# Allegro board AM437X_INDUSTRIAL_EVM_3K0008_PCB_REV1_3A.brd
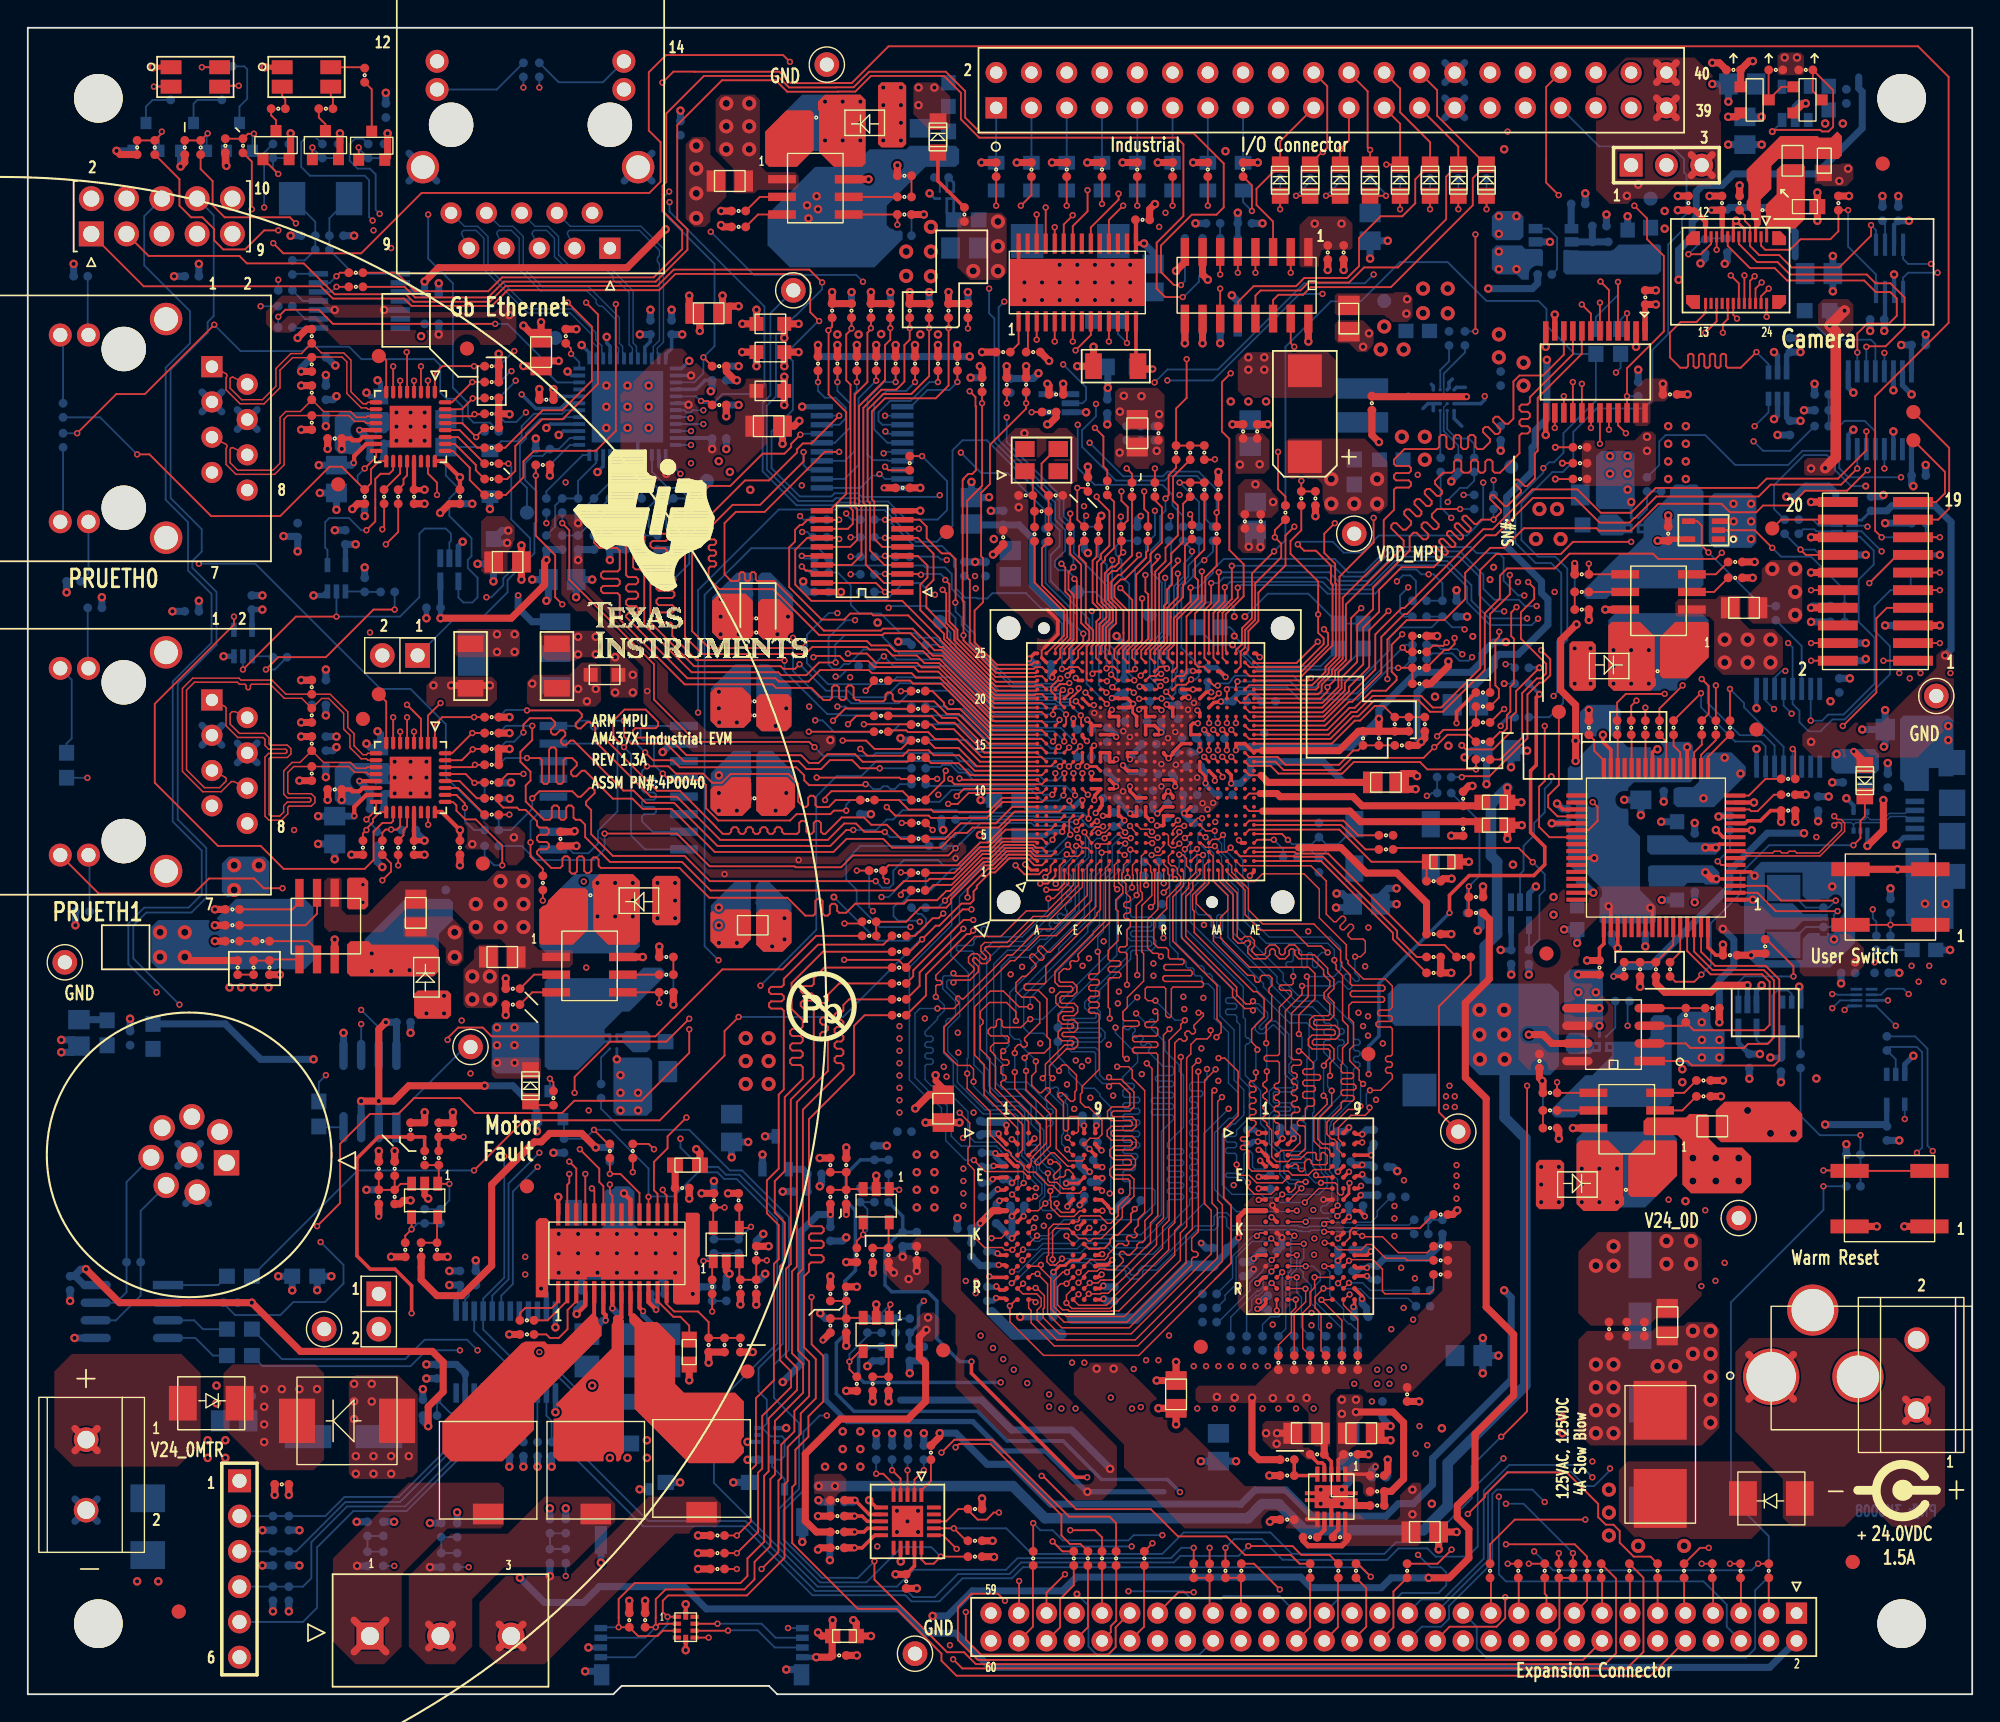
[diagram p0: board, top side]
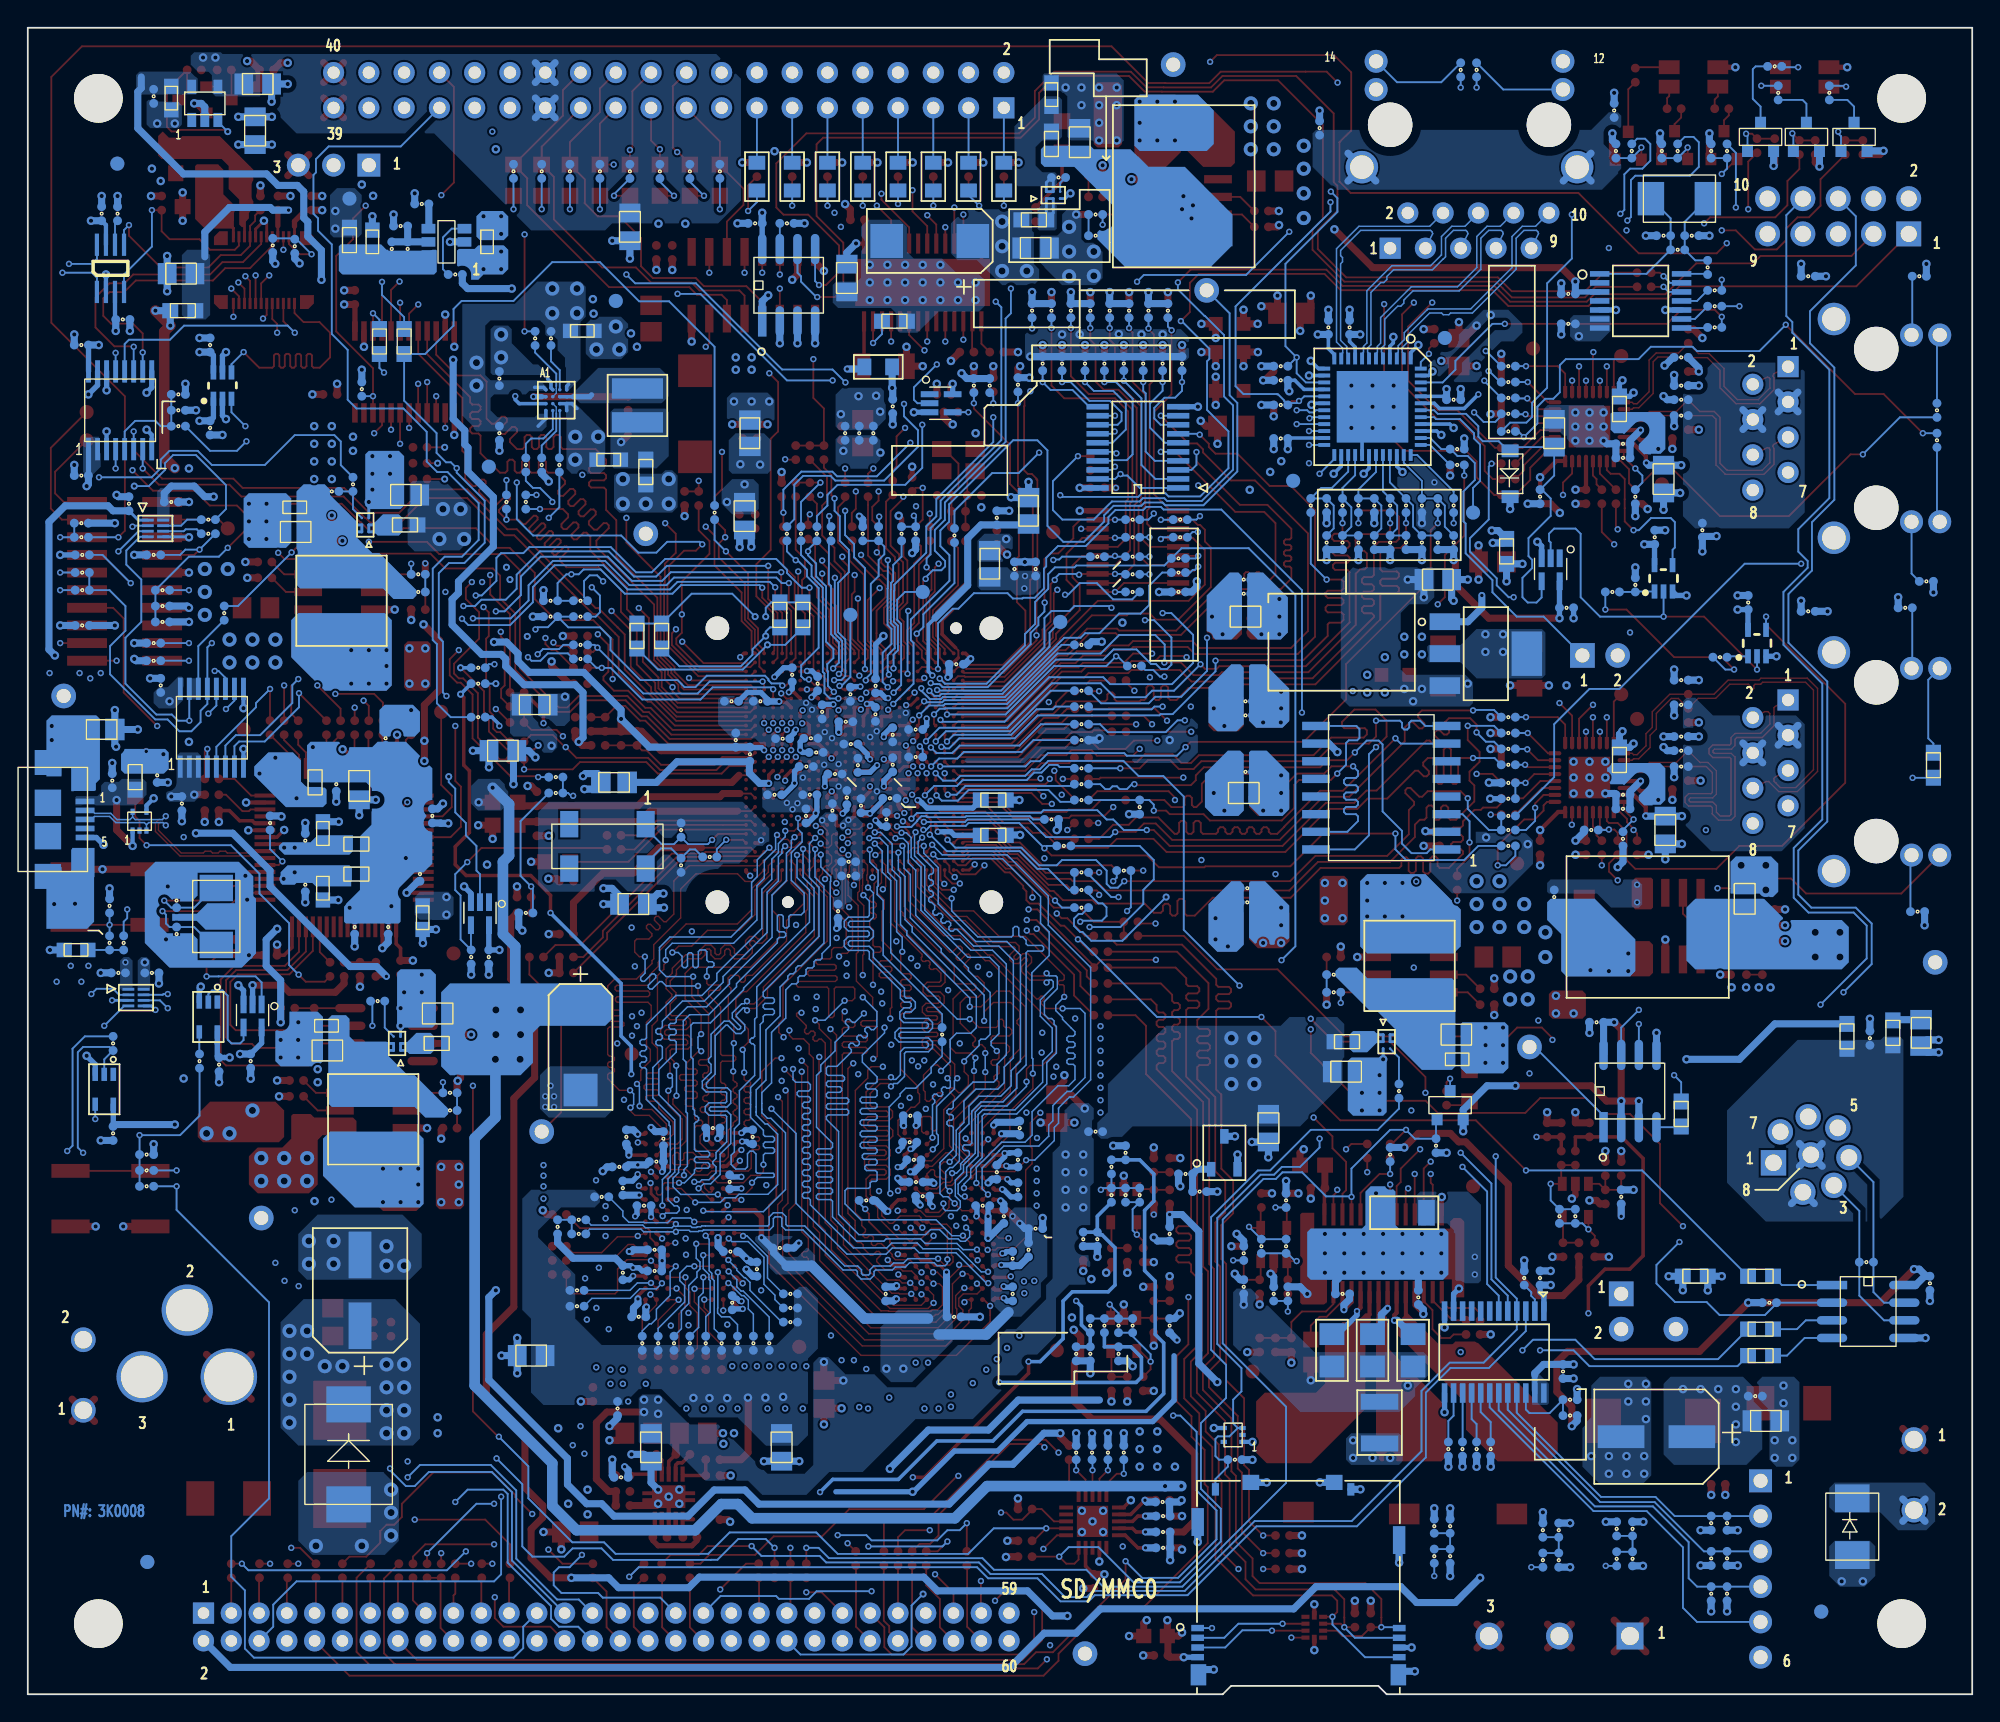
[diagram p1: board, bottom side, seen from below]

Outline 140 x 120 mm; copper layers: TOP, L2_GND, L3_SIG1, L4_SIG2, L5_PWR, BOTTOM. Coordinates in mm from the lower left corner of the outline.
Outline path: 0,120 0,0 42.16,0 42.76,0.6 53.36,0.6 53.96,0 140,0 140,120 0,120

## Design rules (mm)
net group AM437X_CAM0_DATA0: nets AM437X_CAM0_DATA0 N16702915
net group AM437X_CAM0_DATA1: nets AM437X_CAM0_DATA1 N16702921
net group AM437X_MMC0_CLK: nets AM437X_MMC0_CLK MMC_CLK
net group AM437X_MMC0_CMD: nets AM437X_MMC0_CMD MMC_CMD
net group AM437X_MMC0_DAT0: nets AM437X_MMC0_DAT0 MMC_D0
net group AM437X_MMC0_DAT1: nets AM437X_MMC0_DAT1 MMC_D1
net group AM437X_MMC0_DAT2: nets AM437X_MMC0_DAT2 MMC_D2
net group AM437X_MMC0_DAT3: nets AM437X_MMC0_DAT3 MMC_D3
net group AM437X_PRUETH0_MRCLK: nets AM437X_PRUETH0_MRCLK PRUETH0_RXCLK
net group AM437X_PRUETH0_RXD0: nets AM437X_PRUETH0_RXD0 PRUETH0_RXD0
net group AM437X_PRUETH0_RXD1: nets AM437X_PRUETH0_RXD1 PRUETH0_RXD1
net group AM437X_PRUETH0_RXD2: nets AM437X_PRUETH0_RXD2 PRUETH0_RXD2
net group AM437X_PRUETH0_RXD3: nets AM437X_PRUETH0_RXD3 PRUETH0_RXD3
net group AM437X_PRUETH0_RXDV: nets AM437X_PRUETH0_RXDV PRUETH0_RXDV
net group AM437X_PRUETH0_RXER: nets AM437X_PRUETH0_RXER PRUETH0_RXERR
net group AM437X_PRUETH0_TXCLK: nets AM437X_PRUETH0_TXCLK PRUETH0_TXCLK
net group AM437X_PRUETH0_TXD0: nets AM437X_PRUETH0_TXD0 PRUETH0_TXD0
net group AM437X_PRUETH0_TXD1: nets AM437X_PRUETH0_TXD1 PRUETH0_TXD1
net group AM437X_PRUETH0_TXD2: nets AM437X_PRUETH0_TXD2 PRUETH0_TXD2
net group AM437X_PRUETH0_TXD3: nets AM437X_PRUETH0_TXD3 PRUETH0_TXD3
net group AM437X_PRUETH0_TXEN: nets AM437X_PRUETH0_TXEN PRUETH0_TXEN
net group AM437X_PRUETH1_MRCLK: nets AM437X_PRUETH1_MRCLK PRUETH1_RXCLK
net group AM437X_PRUETH1_RXD0: nets AM437X_PRUETH1_RXD0 PRUETH1_RXD0
net group AM437X_PRUETH1_RXD1: nets AM437X_PRUETH1_RXD1 PRUETH1_RXD1
net group AM437X_PRUETH1_RXD2: nets AM437X_PRUETH1_RXD2 PRUETH1_RXD2
net group AM437X_PRUETH1_RXD3: nets AM437X_PRUETH1_RXD3 PRUETH1_RXD3
net group AM437X_PRUETH1_RXDV: nets AM437X_PRUETH1_RXDV PRUETH1_RXDV
net group AM437X_PRUETH1_RXER: nets AM437X_PRUETH1_RXER PRUETH1_RXERR
net group AM437X_PRUETH1_TXCLK: nets AM437X_PRUETH1_TXCLK PRUETH1_TXCLK
net group AM437X_PRUETH1_TXD0: nets AM437X_PRUETH1_TXD0 PRUETH1_TXD0
net group AM437X_PRUETH1_TXD1: nets AM437X_PRUETH1_TXD1 PRUETH1_TXD1
net group AM437X_PRUETH1_TXD2: nets AM437X_PRUETH1_TXD2 PRUETH1_TXD2
net group AM437X_PRUETH1_TXD3: nets AM437X_PRUETH1_TXD3 PRUETH1_TXD3
net group AM437X_PRUETH1_TXEN: nets AM437X_PRUETH1_TXEN PRUETH1_TXEN
net group AM437X_QSPI_CLK: nets AM437X_QSPI_CLK SPIMEM_CLK
net group AM437X_QSPI_CSN: nets AM437X_QSPI_CSN SPIMEM_CS
net group AM437X_QSPI_D0: nets AM437X_QSPI_D0 SPIMEM_D0
net group AM437X_QSPI_D1: nets AM437X_QSPI_D1 SPIMEM_D1
net group AM437X_QSPI_D2: nets AM437X_QSPI_D2 SPIMEM_D2
net group AM437X_QSPI_D3: nets AM437X_QSPI_D3 SPIMEM_D3
net group AM437X_RGMII1_RD0: nets AM437X_RGMII1_RD0 ETH1_RXD0
net group AM437X_RGMII1_RD1: nets AM437X_RGMII1_RD1 ETH1_RXD1
net group AM437X_RGMII1_RD2: nets AM437X_RGMII1_RD2 ETH1_RXD2
net group AM437X_RGMII1_RD3: nets AM437X_RGMII1_RD3 ETH1_RXD3
net group AM437X_RGMII1_RXCLK: nets AM437X_RGMII1_RXCLK ETH1_RXCLK
net group AM437X_RGMII1_RXCTL: nets AM437X_RGMII1_RXCTL ETH1_RXDV
net group AM437X_RGMII1_TD0: nets AM437X_RGMII1_TD0 ETH1_TXD0
net group AM437X_RGMII1_TD1: nets AM437X_RGMII1_TD1 ETH1_TXD1
net group AM437X_RGMII1_TD2: nets AM437X_RGMII1_TD2 ETH1_TXD2
net group AM437X_RGMII1_TD3: nets AM437X_RGMII1_TD3 ETH1_TXD3
net group AM437X_RGMII1_TXCLK: nets AM437X_RGMII1_TXCLK ETH1_TXCLK
net group AM437X_RGMII1_TXCTL: nets AM437X_RGMII1_TXCTL ETH1_TXEN
net group CAM0: nets AM437X_CAM0_HSYNC AM437X_CAM0_VSYNC
net group CAM0_SENSOR: nets SENSOR_HREF SENSOR_VSYNC
net group DDR_CKE: nets DDR_CKE DDR_CKE0
net group AIN: nets AM437X_AIN0 AM437X_AIN1 AM437X_AIN2 AM437X_AIN3 AM437X_AIN4 AM437X_AIN5 AM437X_AIN6 AM437X_AIN7
net group AM437X_PRUETH_MDCLK: nets AM437X_PRUETH_MDCLK PRUETH0_MDC PRUETH1_MDC
net group AM437X_PRUETH_MDDATA: nets AM437X_PRUETH_MDDATA PRUETH0_MDIO PRUETH1_MDIO
net group CLK: nets AM437X_OSC0_IN AM437X_OSC0_OUT ETH1GB_25MHZCLK INDUS_INPUTCLK OSC0_IN OSC0_OUT PRUETH0_25MHZCLK PRUETH1_25MHZCLK RTCK SD0_CLKIN SD_CLKIN XTIN XTOUT
net group DDR_DQM: nets DDR_DQM0 DDR_DQM1 DDR_DQM2 DDR_DQM3
net group IS: nets IS_IHB1 IS_IHB2 IS_IHB3 IS_MIHB1 IS_MIHB2 IS_MIHB3
net group LCD: nets AM437X_LCD_DATA7 AM437X_LCD_HSYNC AM437X_LCD_PCLK SYSBOOT14 SYSBOOT15
net group PWR: nets AGND CAP_VDD_RTC ETH1_LDO_O FT_VBUS FTDI_VPHY FTDI_VPLL MOT_OUT1 MOT_OUT2 MOT_OUT3 MOT_PGND1 MOT_PGND2 MOT_PGND3 N11219802 N11219922 N11220684 N15840029 N16288234 N16739248 N16744367 N16744371 N16744375 N16744379 N16782266 N16839102 N17134629 N17135096 N17814979 V2_8A V2_8D_FB V2_8D_OUT V3_3MTR V3_3MTRB V5_0DENCOD VDD_COREREG VDD_MPU_OUT VDD_MPU_SENSE VDD_MPU_SENSEP VDD_TAMPER VDDA1P8_PMLDO VDDA3P3_PMLDO VDDA_ADC VDDS_CTM VDDS_TAMPER VENDAT VMTR_PWRIN VUSB_FTDI VUSB_JTAG
nets with their own width: min track width 0.102; nets DDR_RESETN
nets with their own width: min track width 0.381; nets V3_3D

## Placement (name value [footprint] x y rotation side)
C1  0.1uF  [SM-7351-CAP-0402]  56.77 113.54 0 top
C2  10uF  [SM-7351-CAP-0805]  127.06 110.42 270 top
C3  0.022uF  [SM-7351-CAP-0402]  69.72 109.79 90 top
C4  0.022uF  [SM-7351-CAP-0402]  72.26 109.79 90 top
C5  0.022uF  [SM-7351-CAP-0402]  74.8 109.79 90 top
C6  0.022uF  [SM-7351-CAP-0402]  77.34 109.79 90 top
C7  0.022uF  [SM-7351-CAP-0402]  79.88 109.79 90 top
C8  0.022uF  [SM-7351-CAP-0402]  82.42 109.79 90 top
C9  0.022uF  [SM-7351-CAP-0402]  84.96 109.79 90 top
C10  0.022uF  [SM-7351-CAP-0402]  87.5 109.79 90 top
C11  2200pF  [SM-7351-CAP-0402]  63.12 109.35 180 top
C12  10uF  [SM-7351-CAP-0805]  50.55 108.97 180 top
C13  0.01uF  [SM-7351-CAP-0402]  119.57 107.38 90 top
C14  0.01uF  [SM-7351-CAP-0402]  121.98 107.38 90 top
C15  0.01uF  [SM-7351-CAP-0402]  124.9 106.87 0 top
C16  0.01uF  [SM-7351-CAP-0402]  80.26 106.17 0 top
C17  0.01uF  [SM-7351-CAP-0402]  51.18 105.66 180 top
C18  0.01uF  [SM-7351-CAP-0402]  93.6 103.82 270 top
C19  1uF  [SM-7351-CAP-0402]  94.74 103.82 270 top
C20  0.01uF  [SM-7351-CAP-0402]  116.46 100.58 90 top
C21  10uF  [SM-7351-CAP-0805]  49.02 99.44 180 top
C22  10uF  [SM-7351-CAP-0805]  36.96 96.65 90 top
C23  10uF  [SM-7351-CAP-1206]  78.33 95.63 0 top
C24  0.01uF  [SM-7351-CAP-0402]  74.04 93.6 0 top
C25  0.01uF  [SM-7351-CAP-0402]  118.24 93.6 0 top
C26  0.1uF  [SM-7351-CAP-0402]  37.34 93.22 180 top
C27  220uF  [SMD7343-122M]  91.95 92.2 90 top
C28  10uF  [SM-7351-CAP-0805]  53.34 91.31 0 top
C29  0.01uF  [SM-7351-CAP-0402]  87.5 90.93 90 top
C30  0.01uF  [SM-7351-CAP-0402]  88.52 90.93 90 top
C31  10uF  [SM-7351-CAP-0805]  79.88 90.8 90 top
C32  0.01uF  [SM-7351-CAP-0402]  81.41 90.8 90 top
C33  0.01uF  [SM-7351-CAP-0402]  22.1 90.42 180 top
C34  0.01uF  [SM-7351-CAP-0402]  62.99 86.87 180 top
C35  24pF  [SM-7351-CAP-0402]  71.85 86.33 180 top
C36  24pF  [SM-7351-CAP-0402]  74.01 86.33 0 top
C37  0.01uF  [SM-7351-CAP-0402]  27.81 86.23 270 top
C38  0.1uF  [SM-7351-CAP-0402]  31.12 86.23 270 top
C39  0.01uF  [SM-7351-CAP-0402]  87.63 84.45 90 top
C40  0.01uF  [SM-7351-CAP-0402]  88.77 84.45 90 top
C41  0.01uF  [SM-7351-CAP-0402]  118.11 83.57 90 top
C43  10uF  [SM-7351-CAP-0805]  34.54 81.53 0 top
C44  0.01uF  [SM-7351-CAP-0402]  122.94 81.53 0 top
C45  10uF  [SM-7351-CAP-0805]  123.57 78.23 0 top
C46  2200pF  [SM-7351-CAP-0402]  111.89 78.11 0 top
C47  0.01uF  [SM-7351-CAP-0402]  52.45 77.47 180 top
C48  0.01uF  [SM-7351-CAP-0402]  52.45 76.45 180 top
C49  47uF  [SM-7351-CAP-1206]  31.88 74.04 90 top
C50  47uF  [SM-7351-CAP-1206]  38.1 74.04 270 top
C51  0.1uF  [SM-7351-CAP-0402]  117.35 73.66 180 top
C52  0.01uF  [SM-7351-CAP-0402]  52.32 71.5 180 top
C53  0.01uF  [SM-7351-CAP-0402]  52.32 70.48 180 top
C54  0.001uF  [SM-7351-CAP-0402]  98.42 69.85 270 top
C55  0.1uF  [SM-7351-CAP-0402]  99.44 69.85 270 top
C56  0.001uF  [SM-7351-CAP-0402]  96.14 68.83 90 top
C57  0.1uF  [SM-7351-CAP-0402]  97.28 68.83 90 top
C58  0.01uF  [SM-7351-CAP-0402]  22.1 65.15 180 top
C59  0.01uF  [SM-7351-CAP-0402]  52.32 64.52 180 top
C60  0.01uF  [SM-7351-CAP-0402]  103.34 64.48 90 top
C61  0.01uF  [SM-7351-CAP-0402]  126.75 63.63 0 top
C62  0.01uF  [SM-7351-CAP-0402]  103.34 62.32 270 top
C63  0.01uF  [SM-7351-CAP-0402]  38.35 61.59 270 top
C64  0.01uF  [SM-7351-CAP-0402]  27.81 60.96 270 top
C65  0.1uF  [SM-7351-CAP-0402]  31.12 60.96 270 top
C66  0.01uF  [SM-7351-CAP-0402]  101.22 58.55 0 top
C67  0.1uF  [SM-7351-CAP-0402]  40.51 57.53 0 top
C68  47nF  [SM-7351-CAP-0402]  104.27 57.4 0 top
C69  0.01uF  [SM-7351-CAP-0402]  14.73 56.52 180 top
C70  10uF  [SM-7351-CAP-0805]  27.94 56.26 270 top
C71  1uF  [SM-7351-CAP-0402]  101.22 54.74 0 top
C72  2200pF  [SM-7351-CAP-0402]  14.73 54.23 180 top
C73  0.01uF  [SM-7351-CAP-0402]  122.56 53.22 0 top
C74  10uF  [SM-7351-CAP-0805]  34.16 53.09 180 top
C75  2200pF  [SM-7351-CAP-0402]  45.97 53.09 180 top
C76  0.01uF  [SM-7351-CAP-0402]  113.16 52.33 270 top
C77  0.01uF  [SM-7351-CAP-0402]  34.92 49.66 180 top
C78  0.1uF  [SM-7351-CAP-0402]  108.84 45.59 270 top
C79  0.01uF  [SM-7351-CAP-0402]  120.65 44.2 0 top
C80  22uF  [SM-7351-CAP-0805]  65.91 42.16 270 top
C81  10uF  [SM-7351-CAP-0805]  121.28 40.89 0 top
C82  2200pF  [SM-7351-CAP-0402]  109.6 40.77 0 top
C83  180pF  [SM-7351-CAP-0402]  27.56 40.64 90 top
C84  180pF  [SM-7351-CAP-0402]  29.59 40.64 90 top
C85  100pF25V10%  [SM-7351-CAP-0402]  58.93 38.1 90 top
C86  100pF25V10%  [SM-7351-CAP-0402]  26.42 37.85 90 top
C87  0.47uF  [SM-7351-CAP-0402]  47.12 36.45 0 top
C88  0.1uF  [SM-7351-CAP-0402]  115.06 36.32 180 top
C89  0.01uF  [SM-7351-CAP-0402]  49.4 35.56 90 top
C90  0.01uF  [SM-7351-CAP-0402]  29.46 32 270 top
C91  100pF25V10%  [SM-7351-CAP-0402]  52.45 31.75 90 top
C92  0.01uF  [SM-7351-CAP-0402]  61.98 31.62 270 top
C93  100pF25V10%  [SM-7351-CAP-0402]  58.93 28.83 90 top
C94  0.01uF  [SM-7351-CAP-0402]  35.94 26.92 0 top
C95  10uF  [SM-7351-CAP-0805]  118.04 26.8 90 top
C96  0.1uF  [SM-7351-CAP-0402]  113.85 26.29 90 top
C97  0.1uF  [SM-7351-CAP-0402]  115.12 26.29 90 top
C98  1uF  [SM-7351-CAP-0402]  116.39 26.29 90 top
C99  0.1uF  [SM-7351-CAP-0402]  35.94 25.91 0 top
C100  0.47uF  [SM-7351-CAP-0402]  50.16 25.15 270 top
C101  0.01uF  [SM-7351-CAP-0402]  61.98 22.35 270 top
C102  22uF  [SM-7351-CAP-0805]  82.68 21.59 270 top
C103  0.1uF  [SM-7351-CAP-0402]  99.31 21.59 270 top
C104  10uF  [SM-7351-CAP-0805]  92.08 18.8 180 top
C105  10uF  [SM-7351-CAP-0805]  96.01 18.8 0 top
C106  0.1uF  [SM-7351-CAP-0402]  92.84 17.27 180 top
C107  0.1uF  [SM-7351-CAP-0402]  95.25 17.27 0 top
C108  10pF  [SM-7351-CAP-0402]  90.68 15.75 180 top
C109  0.001uF  [SM-7351-CAP-0402]  97.16 15.75 0 top
C110  0.001uF  [SM-7351-CAP-0402]  18.29 15.11 0 top
C111  0.001uF  [SM-7351-CAP-0402]  97.16 13.59 180 top
C112  0.1uF  [SM-7351-CAP-0402]  90.68 12.57 180 top
C113  10uF  [SM-7351-CAP-0805]  100.58 11.68 0 top
C114  0.01uF  [SM-7351-CAP-0402]  63.25 8.13 270 top
C115  4.7uF  [SM-7351-CAP-0603]  58.8 4.19 0 top
C116  0.1uF  [SM-7351-CAP-0402]  58.42 2.79 0 top
C117  10uF  [SM-7351-CAP-0805]  123.44 115.95 180 bottom
C118  1uF  [SM-7351-CAP-0603]  66.29 115.19 90 bottom
C119  0.01uF  [SM-7351-CAP-0402]  130.94 115.06 270 bottom
C120  4.7uF  [SM-7351-CAP-0603]  129.67 114.94 270 bottom
C121  0.1uF  [SM-7351-CAP-0402]  25.78 114.05 270 bottom
C122  0.1uF  [SM-7351-CAP-0402]  46.99 112.78 270 bottom
C123  10uF  [SM-7351-CAP-0805]  123.63 112.59 90 bottom
C124  22uF  [SM-7351-CAP-0805]  64.26 111.76 90 bottom
C125  0.1uF  [SM-7351-CAP-0402]  111.63 107.31 0 bottom
C126  0.01uF  [SM-7351-CAP-0402]  134.68 106.61 90 bottom
C127  0.01uF  [SM-7351-CAP-0402]  87.63 105.92 0 bottom
C128  2.2uF  [SM-7351-CAP-0805]  96.65 105.66 270 bottom
C129  18pF  [SM-7351-CAP-0402]  22.23 105.03 180 bottom
C130  18pF  [SM-7351-CAP-0402]  20.19 105.03 0 bottom
C131  220uF  [SMD7343-122M]  75.06 104.65 0 bottom
C132  2.2uF  [SM-7351-CAP-0603]  115.19 104.58 90 bottom
C133  2.2uF  [SM-7351-CAP-0603]  106.93 104.58 90 bottom
C134  10uF  [SM-7351-CAP-0805]  67.44 104.14 180 bottom
C135  15pF  [SM-7351-CAP-0402]  113.79 104.07 90 bottom
C136  10uF  [SM-7351-CAP-0805]  128.97 102.3 0 bottom
C137  4700pF  [SM-7351-CAP-0402]  11.81 102.11 180 bottom
C138  2.2uF  [SM-7351-CAP-0805]  81.03 101.98 270 bottom
C139  0.01uF  [SM-7351-CAP-0402]  29.08 100.84 0 bottom
C140  0.01uF  [SM-7351-CAP-0402]  133.16 98.99 180 bottom
C141  0.01uF  [SM-7351-CAP-0402]  29.08 98.68 0 bottom
C142  0.1uF  [SM-7351-CAP-0402]  46.35 98.42 90 bottom
C143  0.1uF  [SM-7351-CAP-0402]  44.83 98.42 90 bottom
C144  10uF  [SM-7351-CAP-0603]  100.08 98.17 180 bottom
C145  0.01uF  [SM-7351-CAP-0402]  136.14 97.16 0 bottom
C146  0.01uF  [SM-7351-CAP-0402]  126.87 97.16 90 bottom
C147  0.1uF  [SM-7351-CAP-0402]  20.95 96.27 0 bottom
C148  0.1uF  [SM-7351-CAP-0402]  106.05 94.74 90 bottom
C149  0.1uF  [SM-7351-CAP-0402]  49.78 94.61 0 bottom
C150  0.1uF  [SM-7351-CAP-0402]  20.95 94.23 0 bottom
C151  1uF  [SM-7351-CAP-0402]  129.16 93.6 180 bottom
C152  0.01uF  [SM-7351-CAP-0402]  37.34 93.22 180 bottom
C153  0.1uF  [SM-7351-CAP-0402]  20.95 93.22 0 bottom
C154  0.001uF  [SM-7351-CAP-0402]  77.72 92.74 270 bottom
C155  0.1uF  [SM-7351-CAP-0402]  20.95 92.08 0 bottom
C156  0.01uF  [SM-7351-CAP-0402]  126.87 91.19 270 bottom
C157  0.1uF  [SM-7351-CAP-0402]  106.05 90.8 270 bottom
C158  0.01uF  [SM-7351-CAP-0402]  81.15 90.8 90 bottom
C159  0.01uF  [SM-7351-CAP-0402]  80.14 90.8 90 bottom
C160  0.01uF  [SM-7351-CAP-0402]  79.12 90.8 90 bottom
C161  10uF  [SM-7351-CAP-0805]  30.1 90.8 90 bottom
C162  0.1uF  [SM-7351-CAP-0402]  49.78 90.42 0 bottom
C163  0.1uF  [SM-7351-CAP-0402]  25.15 90.04 0 bottom
C164  0.1uF  [SM-7351-CAP-0402]  25.15 89.03 0 bottom
C165  10uF  [SM-7351-CAP-0603]  98.17 88.9 0 bottom
C166  0.01uF  [SM-7351-CAP-0402]  136.14 87.76 0 bottom
C167  10uF  [SM-7351-CAP-0805]  22.23 87.5 270 bottom
C168  10uF  [SM-7351-CAP-0805]  112.78 86.36 0 bottom
C169  0.01uF  [SM-7351-CAP-0402]  129.67 85.85 180 bottom
C170  0.01uF  [SM-7351-CAP-0402]  132.72 85.72 90 bottom
C171  1uF  [SM-7351-CAP-0603]  120.78 85.47 0 bottom
C172  10uF  [SM-7351-CAP-0805]  88.39 84.84 90 bottom
C173  0.01uF  [SM-7351-CAP-0402]  70.23 84.71 90 bottom
C174  0.1uF  [SM-7351-CAP-0402]  136.14 84.33 180 bottom
C175  22uF  [SM-7351-CAP-0805]  120.72 83.69 0 bottom
C176  100pF25V10%  [SM-7351-CAP-0402]  79.88 83.57 90 bottom
C177  100pF25V10%  [SM-7351-CAP-0402]  76.07 83.57 270 bottom
C178  0.01uF  [SM-7351-CAP-0402]  22.86 83.31 90 bottom
C179  0.01uF  [SM-7351-CAP-0402]  68.96 81.03 90 bottom
C180  0.01uF  [SM-7351-CAP-0402]  67.44 81.03 90 bottom
C181  0.01uF  [SM-7351-CAP-0402]  52.45 80.26 180 bottom
C182  10uF  [SM-7351-CAP-0805]  38.48 80.26 180 bottom
C183  0.01uF  [SM-7351-CAP-0402]  57.15 79.38 180 bottom
C184  0.01uF  [SM-7351-CAP-0402]  52.45 79.25 180 bottom
C185  0.01uF  [SM-7351-CAP-0402]  16.13 78.61 90 bottom
C186  1uF  [SM-7351-CAP-0402]  130.3 78.36 180 bottom
C187  0.01uF  [SM-7351-CAP-0402]  29.21 78.23 180 bottom
C188  4700pF  [SM-7351-CAP-0402]  11.81 77.98 180 bottom
C189  10uF  [SM-7351-CAP-0805]  52.32 77.6 180 bottom
C190  0.01uF  [SM-7351-CAP-0402]  136.08 76.96 180 bottom
C191  1uF  [SM-7351-CAP-0402]  64.14 75.56 180 bottom
C192  0.01uF  [SM-7351-CAP-0402]  73.15 74.17 180 bottom
C193  0.01uF  [SM-7351-CAP-0402]  84.96 73.41 90 bottom
C194  0.1uF  [SM-7351-CAP-0402]  20.95 73.02 0 bottom
C195  0.01uF  [SM-7351-CAP-0402]  83.13 72.77 90 bottom
C196  0.01uF  [SM-7351-CAP-0402]  130.43 72.64 90 bottom
C197  0.01uF  [SM-7351-CAP-0402]  78.96 72.61 90 bottom
C198  0.01uF  [SM-7351-CAP-0402]  80.77 72.01 270 bottom
C199  0.01uF  [SM-7351-CAP-0402]  89.33 71.5 0 bottom
C200  0.01uF  [SM-7351-CAP-0402]  87.25 71.5 0 bottom
C201  0.01uF  [SM-7351-CAP-0402]  52.32 71.5 180 bottom
C202  0.01uF  [SM-7351-CAP-0402]  82.8 70.74 270 bottom
C203  0.01uF  [SM-7351-CAP-0402]  78.97 70.56 270 bottom
C204  0.01uF  [SM-7351-CAP-0402]  52.32 70.48 180 bottom
C205  0.01uF  [SM-7351-CAP-0402]  81.1 70.03 180 bottom
C206  0.01uF  [SM-7351-CAP-0402]  76.07 69.47 0 bottom
C207  0.01uF  [SM-7351-CAP-0402]  77.72 69.09 270 bottom
C208  0.1uF  [SM-7351-CAP-0402]  20.95 68.96 0 bottom
C209  0.01uF  [SM-7351-CAP-0402]  114.23 68.83 90 bottom
C210  0.01uF  [SM-7351-CAP-0402]  83.62 68.83 180 bottom
C211  0.01uF  [SM-7351-CAP-0402]  85.65 68.81 0 bottom
C212  1uF  [SM-7351-CAP-0402]  64.14 68.71 180 bottom
C213  0.01uF  [SM-7351-CAP-0402]  80.74 68.42 0 bottom
C214  10uF  [SM-7351-CAP-0805]  105.79 67.95 0 bottom
C215  0.1uF  [SM-7351-CAP-0402]  20.95 67.95 0 bottom
C216  0.01uF  [SM-7351-CAP-0402]  83.24 67.82 180 bottom
C217  0.01uF  [SM-7351-CAP-0402]  88.01 67.69 90 bottom
C218  1uF  [SM-7351-CAP-0402]  76.07 67.49 0 bottom
C219  0.01uF  [SM-7351-CAP-0402]  77.72 66.93 90 bottom
C220  0.01uF  [SM-7351-CAP-0402]  80.23 66.9 90 bottom
C221  0.01uF  [SM-7351-CAP-0402]  83.95 66.8 180 bottom
C222  0.1uF  [SM-7351-CAP-0402]  20.95 66.8 0 bottom
C223  0.01uF  [SM-7351-CAP-0402]  52.32 66.42 180 bottom
C224  0.01uF  [SM-7351-CAP-0402]  81.88 66.26 180 bottom
C225  0.01uF  [SM-7351-CAP-0402]  130.68 66.17 270 bottom
C226  0.01uF  [SM-7351-CAP-0402]  133.92 65.79 90 bottom
C227  0.01uF  [SM-7351-CAP-0402]  117.79 65.53 270 bottom
C228  2.2uF  [SM-7351-CAP-0805]  116.14 65.41 270 bottom
C229  10uF  [SM-7351-CAP-0805]  52.45 64.9 180 bottom
C230  0.01uF  [SM-7351-CAP-0402]  86.23 64.77 0 bottom
C231  0.01uF  [SM-7351-CAP-0402]  83.69 64.77 0 bottom
C232  0.1uF  [SM-7351-CAP-0402]  25.15 64.77 0 bottom
C233  0.01uF  [SM-7351-CAP-0402]  81.03 64.57 90 bottom
C234  0.01uF  [SM-7351-CAP-0402]  77.93 64.52 180 bottom
C235  0.01uF  [SM-7351-CAP-0402]  128.91 64.14 270 bottom
C236  0.01uF  [SM-7351-CAP-0402]  80.01 63.98 90 bottom
C237  0.1uF  [SM-7351-CAP-0402]  25.15 63.75 0 bottom
C238  0.01uF  [SM-7351-CAP-0402]  82.07 63.63 90 bottom
C239  0.01uF  [SM-7351-CAP-0402]  110.87 63.25 90 bottom
C240  0.01uF  [SM-7351-CAP-0402]  83.97 63.25 90 bottom
C241  0.01uF  [SM-7351-CAP-0402]  78.18 62.99 90 bottom
C242  0.01uF  [SM-7351-CAP-0402]  66.29 62.99 180 bottom
C243  15pF  [SM-7351-CAP-0402]  92.96 62.23 90 bottom
C244  10uF  [SM-7351-CAP-0805]  22.1 62.23 270 bottom
C245  4.7uF  [SM-7351-CAP-0603]  118.75 61.98 270 bottom
C246  0.01uF  [SM-7351-CAP-0402]  120.02 61.47 270 bottom
C247  0.01uF  [SM-7351-CAP-0402]  80.9 59.94 0 bottom
C248  15pF  [SM-7351-CAP-0402]  92.96 59.69 270 bottom
C249  0.01uF  [SM-7351-CAP-0402]  111.76 59.06 270 bottom
C250  0.01uF  [SM-7351-CAP-0402]  120.02 58.3 90 bottom
C251  4.7uF  [SM-7351-CAP-0603]  118.75 58.04 90 bottom
C252  0.01uF  [SM-7351-CAP-0402]  52.2 58.04 180 bottom
C253  0.1uF  [SM-7351-CAP-0402]  30.1 57.4 270 bottom
C254  22uF  [SM-7351-CAP-0805]  16.38 57.28 90 bottom
C255  18pF  [SM-7351-CAP-0402]  129.29 57.15 90 bottom
C256  0.01uF  [SM-7351-CAP-0402]  52.2 57.02 180 bottom
C257  10uF  [SM-7351-CAP-0805]  96.39 56.9 0 bottom
C258  4.7uF  [SM-7351-CAP-0603]  111.57 55.92 270 bottom
C259  0.01uF  [SM-7351-CAP-0402]  116.46 55.25 270 bottom
C260  0.01uF  [SM-7351-CAP-0402]  114.05 55.25 90 bottom
C261  18pF  [SM-7351-CAP-0402]  129.29 54.74 270 bottom
C262  1uF  [SM-7351-CAP-0603]  136.53 53.59 0 bottom
C263  0.01uF  [SM-7351-CAP-0402]  106.81 53.09 270 bottom
C264  0.01uF  [SM-7351-CAP-0402]  133.48 51.94 0 bottom
C265  0.01uF  [SM-7351-CAP-0402]  131.06 51.94 180 bottom
C266  10uF  [SM-7351-CAP-0805]  110.49 49.02 0 bottom
C267  0.01uF  [SM-7351-CAP-0402]  27.05 48.39 0 bottom
C268  1uF  [SM-7351-CAP-0603]  118.49 48.13 0 bottom
C269  22uF  [SM-7351-CAP-0805]  37.14 47.5 180 bottom
C270  0.01uF  [SM-7351-CAP-0402]  7.37 47.24 90 bottom
C271  220uF  [SMD7343-122M]  100.2 46.61 270 bottom
C272  22uF  [SM-7351-CAP-0805]  118.43 46.35 0 bottom
C273  1uF  [SM-7351-CAP-0603]  37.08 45.72 180 bottom
C274  0.01uF  [SM-7351-CAP-0402]  123.95 45.59 90 bottom
C275  0.01uF  [SM-7351-CAP-0402]  126.23 45.34 90 bottom
C276  10uF  [SM-7351-CAP-0805]  45.09 44.83 180 bottom
C277  0.01uF  [SM-7351-CAP-0402]  76.45 41.66 0 bottom
C278  0.01uF  [SM-7351-CAP-0402]  90.68 40.77 0 bottom
C279  0.01uF  [SM-7351-CAP-0402]  68.58 40.77 270 bottom
C280  10uF  [SM-7351-CAP-0805]  50.67 40.77 270 bottom
C281  0.01uF  [SM-7351-CAP-0402]  133.86 40.39 270 bottom
C282  0.01uF  [SM-7351-CAP-0402]  96.9 40.13 90 bottom
C283  0.01uF  [SM-7351-CAP-0402]  87.81 40.13 270 bottom
C284  0.01uF  [SM-7351-CAP-0402]  94.23 40 270 bottom
C285  0.01uF  [SM-7351-CAP-0402]  76.5 39.75 0 bottom
C286  180pF  [SM-7351-CAP-0402]  60.96 38.99 90 bottom
C287  1uF  [SM-7351-CAP-0402]  131.44 38.86 180 bottom
C288  0.01uF  [SM-7351-CAP-0402]  76.2 38.48 180 bottom
C289  0.01uF  [SM-7351-CAP-0402]  68.71 38.48 270 bottom
C290  0.01uF  [SM-7351-CAP-0402]  94.74 38.35 180 bottom
C291  0.01uF  [SM-7351-CAP-0402]  97.41 37.97 0 bottom
C292  0.01uF  [SM-7351-CAP-0402]  70.23 37.59 270 bottom
C293  0.47uF  [SM-7351-CAP-0402]  56.64 37.46 0 bottom
C294  0.01uF  [SM-7351-CAP-0402]  89.47 36.89 90 bottom
C295  0.01uF  [SM-7351-CAP-0402]  76.05 36.88 180 bottom
C296  0.01uF  [SM-7351-CAP-0402]  97.16 36.45 270 bottom
C297  0.01uF  [SM-7351-CAP-0402]  68.71 36.32 90 bottom
C298  100pF25V10%  [SM-7351-CAP-0402]  60.96 35.94 90 bottom
C299  0.01uF  [SM-7351-CAP-0402]  75.56 35.86 0 bottom
C300  0.001uF  [SM-7351-CAP-0402]  25.27 35.81 90 bottom
C301  0.01uF  [SM-7351-CAP-0402]  95.63 35.18 180 bottom
C302  0.01uF  [SM-7351-CAP-0402]  71.25 35.18 0 bottom
C303  10uF  [SM-7351-CAP-1206]  40.89 34.67 180 bottom
C304  0.01uF  [SM-7351-CAP-0402]  69.72 34.42 90 bottom
C305  100pF25V10%  [SM-7351-CAP-0402]  29.72 34.42 90 bottom
C306  0.1uF  [SM-7351-CAP-0402]  101.85 33.66 270 bottom
C307  0.1uF  [SM-7351-CAP-0402]  67.44 33.53 180 bottom
C308  0.001uF  [SM-7351-CAP-0402]  57.78 33.15 270 bottom
C309  180pF  [SM-7351-CAP-0402]  64.01 32.77 270 bottom
C310  100pF25V10%  [SM-7351-CAP-0402]  51.18 32.26 270 bottom
C311  0.1uF  [SM-7351-CAP-0402]  85.85 32.13 180 bottom
C312  0.1uF  [SM-7351-CAP-0402]  94.87 32 0 bottom
C313  0.1uF  [SM-7351-CAP-0402]  67.95 32 90 bottom
C314  0.01uF  [SM-7351-CAP-0402]  89.41 31.88 180 bottom
C315  0.01uF  [SM-7351-CAP-0402]  69.09 31.37 90 bottom
C316  0.01uF  [SM-7351-CAP-0402]  87.5 30.61 90 bottom
C317  0.1uF  [SM-7351-CAP-0402]  94.87 30.48 180 bottom
C318  0.01uF  [SM-7351-CAP-0402]  97.16 30.35 270 bottom
C319  0.01uF  [SM-7351-CAP-0402]  31.12 29.97 90 bottom
C320  0.01uF  [SM-7351-CAP-0402]  3.05 29.59 270 bottom
C321  0.001uF  [SM-7351-CAP-0402]  52.45 29.34 90 bottom
C322  100uF  [CAP-ALUM-D6XL7]  116.08 29.08 90 bottom
C323  0.01uF  [SM-7351-CAP-0402]  78.23 28.83 270 bottom
C324  0.01uF  [SM-7351-CAP-0402]  69.09 28.83 270 bottom
C325  180pF  [SM-7351-CAP-0402]  49.28 28.83 90 bottom
C326  0.1uF  [SM-7351-CAP-0402]  45.34 28.83 0 bottom
C327  0.1uF  [SM-7351-CAP-0402]  39.88 28.58 90 bottom
C328  0.01uF  [SM-7351-CAP-0402]  89.28 28.19 270 bottom
C329  0.01uF  [SM-7351-CAP-0402]  96.01 27.18 180 bottom
C330  0.1uF  [SM-7351-CAP-0402]  73.31 27.17 180 bottom
C331  100pF25V10%  [SM-7351-CAP-0402]  61.47 26.54 90 bottom
C332  0.001uF  [SM-7351-CAP-0402]  57.78 26.54 90 bottom
C333  180pF  [SM-7351-CAP-0402]  63.5 24.51 270 bottom
C334  180pF  [SM-7351-CAP-0402]  61.47 24.51 270 bottom
C335  10uF  [SM-7351-CAP-0805]  103.76 24.38 0 bottom
C336  0.01uF  [SM-7351-CAP-0402]  29.46 23.24 270 bottom
C337  0.1uF  [SM-7351-CAP-0402]  15.62 21.46 180 bottom
C338  0.1uF  [SM-7351-CAP-0402]  97.54 20.57 270 bottom
C339  10uF  [SM-7351-CAP-0805]  14.86 19.69 180 bottom
C340  100uF  [CAP-ALUM-D6XL7]  22.73 18.54 0 bottom
C341  10uF  [SM-7351-CAP-0805]  95.12 17.78 270 bottom
C342  10uF  [SM-7351-CAP-0805]  85.72 17.78 270 bottom
C343  0.01uF  [SM-7351-CAP-0402]  64.52 17.4 90 bottom
C344  0.01uF  [SM-7351-CAP-0402]  63.37 17.4 90 bottom
C345  0.01uF  [SM-7351-CAP-0402]  62.23 17.4 90 bottom
C346  0.01uF  [SM-7351-CAP-0402]  61.09 17.4 90 bottom
C347  0.001uF  [SM-7351-CAP-0402]  18.8 12.32 270 bottom
C348  47nF  [SM-7351-CAP-0402]  38.73 12.1 90 bottom
C349  47nF  [SM-7351-CAP-0402]  24.46 11.91 90 bottom
C350  47nF  [SM-7351-CAP-0402]  30.91 11.82 90 bottom
C351  0.001uF  [SM-7351-CAP-0402]  18.8 9.78 270 bottom
C352  0.001uF  [SM-7351-CAP-0402]  18.8 7.24 270 bottom
D1  MBR0530T1  [SOD-123]  60.26 113.16 180 top
D2  Green LED  [SM_LED_0805]  65.53 112.14 90 top
D3  Green LED  [SM_LED_0805]  90.17 109.03 90 top
D4  Green LED  [SM_LED_0805]  92.33 109.03 90 top
D5  Green LED  [SM_LED_0805]  94.49 109.03 90 top
D6  Green LED  [SM_LED_0805]  96.65 109.03 90 top
D7  Green LED  [SM_LED_0805]  98.81 109.03 90 top
D8  Green LED  [SM_LED_0805]  100.97 109.03 90 top
D9  Green LED  [SM_LED_0805]  103 109.03 90 top
D10  Green LED  [SM_LED_0805]  105.03 109.03 90 top
D11  MBR0530T1  [SOD-123]  113.86 74.04 0 top
D12  Green LED  [SM_LED_0805]  132.27 65.79 270 top
D13  MBR0530T1  [SOD-123]  44 57.15 180 top
D14  MBR0530T1  [SOD-123]  28.7 51.63 90 top
D15  Red LED  [SM_LED_0805]  36.2 43.81 90 top
D16  MBR0530T1  [SOD-123]  111.57 36.7 0 top
D17  -  [MBRS140T]  13.21 20.95 180 top
D18  -  [SMCJ26CA]  22.99 19.69 0 top
D19  -  [MBRS140T]  125.54 14.1 0 top
D20  MMSD103T1  [SOD-123]  33.27 87.88 270 bottom
D21  -  [SMCJ26CA]  116.9 17.27 270 bottom
D22  -  [MBRS140T]  8.64 12.07 270 bottom
F1  Fuse 4A  [SMDFUSEBLK]  117.54 17.27 90 top
FB1  150OHM800mA  [SM-7351-IND-0805]  95.12 99.06 90 top
FB2  600mAFB10ohm  [HF70ACB201209]  53.47 98.68 180 top
FB3  600mAFB10ohm  [HF70ACB201209]  53.47 96.65 180 top
FB4  600mAFB10ohm  [HF70ACB201209]  53.47 93.85 180 top
FB5  600mAFB10ohm  [HF70ACB201209]  41.53 73.41 180 top
FB6  150OHM800mA  [SM-7351-IND-0805]  97.79 65.66 0 top
FB7  150OHM800mA  [SM-7351-IND-0805]  52.2 55.37 180 top
FB8  150OHM800mA  [SM-7351-IND-0805]  88.01 90.8 270 bottom
FB9  150OHM800mA  [SM-7351-IND-0805]  67.95 85.22 270 bottom
FB10  150OHM800mA  [SM-7351-IND-0805]  70.74 81.41 270 bottom
FB11  150OHM800mA  [SM-7351-IND-0805]  103.5 71.25 0 bottom
FB12  150OHM800mA  [SM-7351-IND-0805]  134.68 69.47 180 bottom
FB13  220OHM2A  [SM-7351-IND-0603]  132.27 66.04 90 bottom
FB14  150OHM800mA  [SM-7351-IND-0805]  97.79 65.66 0 bottom
FB15  220OHM2A  [SM-7351-IND-0603]  116.34 61.22 180 bottom
FB16  220OHM2A  [SM-7351-IND-0603]  116.34 59.06 180 bottom
FB17  150OHM800mA  [SM-7351-IND-0805]  3.68 47.62 90 bottom
J1  Header 20x2 Female  [HDR2X20-335M]  69.72 114.23 0 top
J2  HEADER 3  [HEADER_3X1]  115.44 110.11 0 top
J3  HEADER 5x2  [HDR2X5-330M]  4.57 105.16 90 top
J4  RJ-45 Gigabit  [CNRJ45-1X1WLED-598M]  41.91 104.13 180 top
J5  AXK7L24223G  [SCKAXK7L24]  123 102.55 180 top
J6  RJ-45 10_100Mb  [CNRJ45-1X1WLED]  13.26 95.6 270 top
J7  CTI JTAG  [HEADER10X2]  133.03 80.14 90 top
J8  HEADER 2  [HEADER_2X1]  28.07 74.8 90 top
J9  RJ-45 10_100Mb  [CNRJ45-1X1WLED]  13.26 71.59 270 top
J10  43-01028  [CN43-01028]  14.31 38.27 180 top
J11  HEADER 2  [HEADER_2X1]  25.27 28.83 180 top
J12  Power Jack RAPC722X  [RAPC712]  125.52 22.86 180 top
J13  Connector_Screwdown  [CONN_OSTTC02]  136 20.45 90 top
J14  Connector_Screwdown  [CONN_OSTTC02]  4.2 18.33 270 top
J15  HEADER 6  [HDRTSW1X6-330M]  15.24 15.37 270 top
J16  Header_30x2_Female  [HDR2X30-2MM-177M]  127.35 5.84 180 top
J17  Connector_Screwdown  [CNOSTTC03]  24.64 4.19 0 top
J18  USB_MicroAB  [ZX62-AB-5PA]  135.88 62.99 270 bottom
J19  SCHA5B0200  [SD-MICRO-SCHA5B0300]  48.51 4.76 180 bottom
L1  4.7uH  [SMD_SLF7055T]  48.51 16.26 270 top
L2  4.7uH  [SMD_SLF7055T]  33.15 16.13 270 top
L3  4.7uH  [SMD_SLF7055T]  40.89 16.13 270 top
L4  47uH  [INDMSS1038]  56.77 108.58 180 bottom
L5  1uH  [IND4X4-83M]  96.11 92.8 270 bottom
L6  100uH  [INDMSS6132]  117.41 78.74 0 bottom
L7  100uH  [INDMSS1038]  23.37 55.24 90 bottom
L8  82uH  [INDMSS6122]  40.51 52.45 180 bottom
L9  47uH  [INDMSS6132]  115.13 41.4 0 bottom
NOREF  -  [unnamed]  109.35 53.34 0 top
NOREF#2  -  [unnamed#2]  5.08 5.08 0 top
NOREF#3  -  [#3]  140 0 90 top
NOREF#4  -  [unnamed]  65.91 24.77 0 top
NOREF#5  -  [unnamed]  131.39 9.53 0 top
NOREF#6  -  [unnamed]  22.35 87.12 0 top
NOREF#7  -  [unnamed]  10.87 5.95 0 top
NOREF#8  -  [unnamed]  24.13 70.23 0 top
NOREF#9  -  [unnamed#2]  134.92 5.08 0 top
NOREF#10  -  [unnamed]  133.55 110.22 0 top
NOREF#11  -  [unnamed]  32.77 59.82 0 top
NOREF#12  -  [unnamed#2]  5.08 114.92 0 top
NOREF#13  -  [#3]  -26.19 -201.65 0 top
NOREF#14  -  [unnamed#2]  134.92 114.92 0 top
NOREF#15  -  [unnamed]  31.62 96.9 0 top
NOREF#16  -  [unnamed]  84.45 25.02 0 top
NOREF#17  -  [unnamed]  51.82 23.24 0 top
NOREF#18  -  [unnamed]  35.94 36.58 0 top
NOREF#19  -  [#3]  0 120 0 top
NOREF#20  -  [unnamed]  96.52 46.1 0 top
NOREF#21  -  [unnamed]  124.46 69.47 0 top
NOREF#22  -  [unnamed]  66.17 83.69 0 top
NOREF#23  -  [#3]  57.15 49.53 0 top
NOREF#24  -  [unnamed]  131.39 9.53 180 bottom
NOREF#25  -  [unnamed]  133.55 110.22 180 bottom
NOREF#26  -  [unnamed]  48.89 87.38 180 bottom
NOREF#27  -  [unnamed]  97.66 100.33 180 bottom
NOREF#28  -  [unnamed]  37.97 97.66 180 bottom
NOREF#29  -  [unnamed]  10.87 5.95 180 bottom
NOREF#30  -  [unnamed]  106.81 88.39 180 bottom
Q1  BSS138  [SOT23-3]  124.33 114.81 270 top
Q2  BSS138  [SOT23-3]  128.14 114.81 270 top
Q3  BSS138  [SOT23-3]  17.87 111.55 0 top
Q4  BSS138  [SOT23-3]  21.43 111.55 0 top
Q5  BSS138  [SOT23-3]  24.77 111.51 0 top
Q6  BSS138  [SOT23-3]  15.24 112.14 180 bottom
Q7  BSS138  [SOT23-3]  11.94 112.14 180 bottom
Q8  BSS138  [SOT23-3]  8.51 112.14 180 bottom
Q9  FDT434P  [SOT223-4]  35.02 74.93 180 bottom
Q10  BSS84  [SOT23-3]  37.59 42.42 180 bottom
R1  100K  [SM-7351-RES-0402]  122.81 116.97 0 top
R2  10K  [SM-7351-RES-0402]  125.86 116.97 0 top
R3  10K  [SM-7351-RES-0402]  128.02 116.97 180 top
R4  150  [SM-7351-RES-0402]  24.26 116.59 90 top
R5  150  [SM-7351-RES-0402]  18.03 114.17 0 top
R6  150  [SM-7351-RES-0402]  21.46 114.17 0 top
R7  100K  [SM-7351-RES-0402]  14.22 111.51 90 top
R8  0  [SM-7351-RES-0402]  15.49 111.51 90 top
R9  100K  [SM-7351-RES-0402]  7.87 111.38 90 top
R10  0  [SM-7351-RES-0402]  9.14 111.38 270 top
R11  100K  [SM-7351-RES-0402]  11.3 111.38 90 top
R12  0  [SM-7351-RES-0402]  12.45 111.38 90 top
R13  0  [SM-7351-RES-0603]  129.35 110.42 90 top
R14  34K  [SM-7351-RES-0402]  63.12 107.82 180 top
R15  4.7K  [SM-7351-RES-0402]  123.25 107.38 90 top
R16  4.7K  [SM-7351-RES-0402]  130.36 107.38 90 top
R17  0  [SM-7351-RES-0603]  127.95 107.12 180 top
R18  51K  [SM-7351-RES-0402]  51.18 106.81 0 top
R19  4.75K, 1%  [SM-7351-RES-0402]  63.12 106.55 0 top
R20  33  [SM-7351-RES-0402]  67.44 106.55 270 top
R21  0  [SM-7351-RES-0402]  23.62 102.36 0 top
R22  0  [SM-7351-RES-0402]  23.62 101.35 0 top
R23  100K  [SM-7351-RES-0402]  57.91 99.63 90 top
R24  100K  [SM-7351-RES-0402]  59.31 99.63 90 top
R25  100K  [SM-7351-RES-0402]  60.71 99.63 90 top
R26  100K  [SM-7351-RES-0402]  62.1 99.63 90 top
R27  100K  [SM-7351-RES-0402]  63.5 99.63 90 top
R28  100K  [SM-7351-RES-0402]  64.9 99.63 90 top
R29  100K  [SM-7351-RES-0402]  66.29 99.63 90 top
R30  100K  [SM-7351-RES-0402]  67.69 99.63 90 top
R31  49.9  [SM-7351-RES-0402]  20.45 97.79 270 top
R32  12.1K, 1%  [SM-7351-RES-0402]  38.73 97.79 90 top
R33  0  [SM-7351-RES-0402]  70.23 96.65 0 top
R34  0  [SM-7351-RES-0402]  72.39 96.65 180 top
R35  100K  [SM-7351-RES-0402]  56.9 95.82 90 top
R36  100K  [SM-7351-RES-0402]  58.29 95.82 90 top
R37  100K  [SM-7351-RES-0402]  59.69 95.82 90 top
R38  100K  [SM-7351-RES-0402]  61.09 95.82 90 top
R39  100K  [SM-7351-RES-0402]  62.48 95.82 90 top
R40  100K  [SM-7351-RES-0402]  63.88 95.82 90 top
R41  100K  [SM-7351-RES-0402]  65.53 95.82 90 top
R42  100K  [SM-7351-RES-0402]  66.93 95.82 90 top
R43  49.9  [SM-7351-RES-0402]  20.45 95.76 90 top
R44  2.2K  [SM-7351-RES-0402]  33.4 95.63 180 top
R45  1K  [SM-7351-RES-0402]  49.78 95.63 180 top
R46  2.2K  [SM-7351-RES-0402]  33.4 94.49 180 top
R47  100K  [SM-7351-RES-0402]  68.71 94.29 90 top
R48  100K  [SM-7351-RES-0402]  70.48 94.29 90 top
R49  100K  [SM-7351-RES-0402]  71.88 94.29 90 top
R50  49.9  [SM-7351-RES-0402]  20.45 93.73 270 top
R51  2.2K  [SM-7351-RES-0402]  33.4 93.34 180 top
R52  0  [SM-7351-RES-0402]  96.77 92.96 90 top
R53  1K  [SM-7351-RES-0402]  49.78 92.84 180 top
R54  10K  [SM-7351-RES-0402]  73.53 92.33 0 top
R55  2.2K  [SM-7351-RES-0402]  33.4 92.2 180 top
R56  49.9  [SM-7351-RES-0402]  20.45 91.57 90 top
R57  2.2K  [SM-7351-RES-0402]  33.4 91.19 180 top
R58  4.02K  [SM-7351-RES-0402]  111.76 89.79 180 top
R59  0  [SM-7351-RES-0402]  33.4 89.76 0 top
R60  0  [SM-7351-RES-0402]  82.68 89.41 90 top
R61  0  [SM-7351-RES-0402]  83.69 89.41 90 top
R62  0  [SM-7351-RES-0402]  84.71 89.41 90 top
R63  0  [SM-7351-RES-0402]  63.5 88.65 270 top
R64  4.02K  [SM-7351-RES-0402]  111.76 88.65 180 top
R65  0  [SM-7351-RES-0402]  33.4 88.61 0 top
R66  1.5K  [SM-7351-RES-0402]  37.08 88.52 0 top
R67  0  [SM-7351-RES-0402]  33.4 87.5 0 top
R68  4.02K  [SM-7351-RES-0402]  111.76 87.5 180 top
R69  10K  [SM-7351-RES-0402]  76.33 87.12 90 top
R70  0  [SM-7351-RES-0402]  77.72 86.87 90 top
R71  0  [SM-7351-RES-0402]  79.5 86.74 90 top
R72  0  [SM-7351-RES-0402]  81.15 86.74 90 top
R73  0  [SM-7351-RES-0402]  83.69 86.74 90 top
R74  0  [SM-7351-RES-0402]  84.71 86.74 90 top
R75  10K  [SM-7351-RES-0402]  85.72 86.74 90 top
R76  0  [SM-7351-RES-0402]  33.4 86.36 0 top
R77  2.2K  [SM-7351-RES-0402]  24.26 86.23 270 top
R78  0  [SM-7351-RES-0402]  25.65 86.23 270 top
R79  0  [SM-7351-RES-0402]  26.67 86.23 270 top
R80  0  [SM-7351-RES-0402]  91.69 86.11 90 top
R81  10K  [SM-7351-RES-0402]  92.71 86.11 90 top
R82  1M  [SM-7351-RES-0402]  72.99 85.18 0 top
R83  0  [SM-7351-RES-0402]  90.55 85.09 90 top
R84  0  [SM-7351-RES-0402]  83.82 83.69 270 top
R85  0  [SM-7351-RES-0402]  75.06 83.57 270 top
R86  0  [SM-7351-RES-0402]  76.07 83.57 90 top
R87  0  [SM-7351-RES-0402]  77.09 83.57 90 top
R88  0  [SM-7351-RES-0402]  78.74 83.57 90 top
R89  0  [SM-7351-RES-0402]  80.64 83.57 90 top
R90  0  [SM-7351-RES-0402]  85.6 83.57 90 top
R91  0  [SM-7351-RES-0402]  72.48 83.53 90 top
R92  0  [SM-7351-RES-0402]  73.5 83.53 90 top
R93  8.06K  [SM-7351-RES-0402]  111.89 80.64 180 top
R94  51K  [SM-7351-RES-0402]  122.94 80.39 180 top
R95  60.4K  [SM-7351-RES-0402]  111.89 79.38 180 top
R96  2.2K  [SM-7351-RES-0402]  100.2 76.2 0 top
R97  0  [SM-7351-RES-0402]  100.2 75.06 180 top
R98  0  [SM-7351-RES-0402]  100.2 73.91 180 top
R99  0  [SM-7351-RES-0402]  61.43 72.99 0 top
R100  2.2K  [SM-7351-RES-0402]  100.2 72.77 0 top
R101  49.9  [SM-7351-RES-0402]  20.45 72.52 270 top
R102  22  [SM-7351-RES-0402]  64.1 72.23 0 top
R103  0  [SM-7351-RES-0402]  104.77 72.14 180 top
R104  0  [SM-7351-RES-0402]  104.77 71.12 180 top
R105  0  [SM-7351-RES-0402]  64.1 70.96 0 top
R106  49.9  [SM-7351-RES-0402]  20.45 70.48 90 top
R107  22  [SM-7351-RES-0402]  61.43 70.45 0 top
R108  2.2K  [SM-7351-RES-0402]  33.4 70.36 180 top
R109  0  [SM-7351-RES-0402]  104.77 69.98 180 top
R110  0  [SM-7351-RES-0402]  100.58 69.85 90 top
R111  0  [SM-7351-RES-0402]  64.1 69.82 0 top
R112  0  [SM-7351-RES-0402]  112.4 69.6 270 top
R113  0  [SM-7351-RES-0402]  114.43 69.6 270 top
R114  0  [SM-7351-RES-0402]  115.45 69.6 270 top
R115  0  [SM-7351-RES-0402]  116.46 69.6 270 top
R116  0  [SM-7351-RES-0402]  117.48 69.6 270 top
R117  0  [SM-7351-RES-0402]  118.5 69.6 270 top
R118  0  [SM-7351-RES-0402]  120.53 69.6 270 top
R119  0  [SM-7351-RES-0402]  121.54 69.6 270 top
R120  0  [SM-7351-RES-0402]  122.56 69.6 270 top
R121  22  [SM-7351-RES-0402]  61.43 69.31 0 top
R122  2.2K  [SM-7351-RES-0402]  33.4 69.22 180 top
R123  22  [SM-7351-RES-0402]  64.1 68.67 0 top
R124  0  [SM-7351-RES-0402]  104.77 68.58 180 top
R125  49.9  [SM-7351-RES-0402]  20.45 68.45 270 top
R126  0  [SM-7351-RES-0402]  98.93 68.33 180 top
R127  2.2K  [SM-7351-RES-0402]  33.4 68.07 180 top
R128  0  [SM-7351-RES-0402]  64.14 67.44 0 top
R129  0  [SM-7351-RES-0402]  104.77 67.31 180 top
R130  2.2K  [SM-7351-RES-0402]  33.4 66.93 180 top
R131  49.9  [SM-7351-RES-0402]  20.45 66.29 90 top
R132  0  [SM-7351-RES-0402]  64.14 65.91 180 top
R133  0  [SM-7351-RES-0402]  126.75 65.91 180 top
R134  0  [SM-7351-RES-0402]  33.4 65.66 180 top
R135  10K  [SM-7351-RES-0402]  126.75 64.77 0 top
R136  0  [SM-7351-RES-0402]  33.4 64.52 0 top
R137  0  [SM-7351-RES-0402]  60.45 64.39 0 top
R138  0  [SM-7351-RES-0402]  64.14 64.39 180 top
R139  0  [SM-7351-RES-0603]  105.63 64.23 0 top
R140  0  [SM-7351-RES-0402]  33.4 63.34 0 top
R141  0  [SM-7351-RES-0402]  64.14 62.74 0 top
R142  0  [SM-7351-RES-0603]  105.63 62.58 0 top
R143  0  [SM-7351-RES-0402]  97.79 61.85 180 top
R144  0  [SM-7351-RES-0402]  64.14 61.59 0 top
R145  2.2K  [SM-7351-RES-0402]  24.13 60.96 270 top
R146  0  [SM-7351-RES-0402]  25.53 60.96 270 top
R147  0  [SM-7351-RES-0402]  26.67 60.96 270 top
R148  0  [SM-7351-RES-0402]  97.79 60.83 180 top
R149  0  [SM-7351-RES-0603]  101.85 59.94 0 top
R150  0  [SM-7351-RES-0402]  61.09 59.31 0 top
R151  0  [SM-7351-RES-0402]  64.1 59.15 0 top
R152  0  [SM-7351-RES-0402]  37.08 58.42 270 top
R153  0  [SM-7351-RES-0402]  64.1 57.88 0 top
R154  95.3K  [SM-7351-RES-0402]  104.27 56.26 0 top
R155  0  [SM-7351-RES-0402]  60.58 55.63 0 top
R156  51K  [SM-7351-RES-0402]  14.73 55.37 0 top
R157  0  [SM-7351-RES-0402]  60.58 54.61 180 top
R158  0  [SM-7351-RES-0402]  62.74 54.61 0 top
R159  49.9K  [SM-7351-RES-0402]  16.89 54.23 0 top
R160  4.7K  [SM-7351-RES-0402]  125.09 53.85 90 top
R161  0  [SM-7351-RES-0402]  62.74 53.47 0 top
R162  49.9  [SM-7351-RES-0402]  101.22 53.09 180 top
R163  0  [SM-7351-RES-0402]  103.38 53.09 180 top
R164  49.9  [SM-7351-RES-0402]  15.11 52.32 90 top
R165  16K  [SM-7351-RES-0402]  16.26 52.32 270 top
R166  3.01K  [SM-7351-RES-0402]  17.4 52.32 90 top
R167  0  [SM-7351-RES-0402]  62.74 52.32 0 top
R168  4.7K  [SM-7351-RES-0402]  114.94 52.2 270 top
R169  10K  [SM-7351-RES-0402]  116.08 52.2 90 top
R170  0  [SM-7351-RES-0402]  117.23 52.2 90 top
R171  220  [SM-7351-RES-0402]  118.24 52.2 270 top
R172  10K  [SM-7351-RES-0402]  101.22 51.94 180 top
R173  49.9K  [SM-7351-RES-0402]  45.97 51.82 180 top
R174  0  [SM-7351-RES-0402]  62.74 51.18 0 top
R175  51K  [SM-7351-RES-0402]  34.92 50.8 0 top
R176  20.5K  [SM-7351-RES-0402]  45.97 50.55 180 top
R177  0  [SM-7351-RES-0402]  62.74 50.04 0 top
R178  10K  [SM-7351-RES-0402]  121.28 49.4 0 top
R179  0  [SM-7351-RES-0402]  62.74 48.89 0 top
R180  2.2K  [SM-7351-RES-0402]  119.38 48.89 90 top
R181  40.2K  [SM-7351-RES-0402]  109.6 43.31 0 top
R182  51K  [SM-7351-RES-0402]  120.65 43.05 180 top
R183  220  [SM-7351-RES-0402]  37.85 42.93 90 top
R184  22K  [SM-7351-RES-0402]  109.6 42.04 0 top
R185  22K  [SM-7351-RES-0402]  30.61 40.64 270 top
R186  0  [SM-7351-RES-0402]  41.91 39.12 270 top
R187  0  [SM-7351-RES-0402]  43.56 39.12 270 top
R188  22K  [SM-7351-RES-0402]  28.58 38.61 270 top
R189  22K  [SM-7351-RES-0402]  29.59 38.61 270 top
R190  0  [SM-7351-RES-0603]  47.5 38.1 0 top
R191  49.9K  [SM-7351-RES-0402]  57.78 38.1 270 top
R192  49.9K  [SM-7351-RES-0402]  25.27 37.85 270 top
R193  1K  [SM-7351-RES-0402]  25.27 35.81 270 top
R194  28.7K  [SM-7351-RES-0402]  26.42 35.81 270 top
R195  1K  [SM-7351-RES-0402]  57.78 35.81 270 top
R196  28.7K  [SM-7351-RES-0402]  58.93 35.81 270 top
R197  1K  [SM-7351-RES-0402]  51.18 35.56 90 top
R198  240  [SM-7351-RES-0402]  101.73 34.54 180 top
R199  47  [SM-7351-RES-0402]  101.73 32.26 180 top
R200  1K  [SM-7351-RES-0402]  27.18 32 270 top
R201  33  [SM-7351-RES-0402]  28.32 32 270 top
R202  0  [SM-7351-RES-0402]  64.01 31.75 90 top
R203  1K  [SM-7351-RES-0402]  59.69 31.62 270 top
R204  33  [SM-7351-RES-0402]  60.83 31.62 270 top
R205  47  [SM-7351-RES-0402]  101.73 31.24 180 top
R206  47  [SM-7351-RES-0402]  101.73 30.23 180 top
R207  22K  [SM-7351-RES-0402]  49.28 29.34 90 top
R208  28.7K  [SM-7351-RES-0402]  51.31 29.34 270 top
R209  1K  [SM-7351-RES-0402]  52.45 29.34 270 top
R210  28.7K  [SM-7351-RES-0402]  57.78 28.83 90 top
R211  1K  [SM-7351-RES-0402]  57.78 26.54 270 top
R212  49.9K  [SM-7351-RES-0402]  58.93 26.54 90 top
R213  4.99K  [SM-7351-RES-0402]  49.02 25.15 90 top
R214  402K  [SM-7351-RES-0402]  51.31 25.15 270 top
R215  0  [SM-7351-RES-0603]  47.62 24.64 90 top
R216  47  [SM-7351-RES-0402]  90.04 23.88 90 top
R217  47  [SM-7351-RES-0402]  91.19 23.88 90 top
R218  47  [SM-7351-RES-0402]  92.33 23.88 90 top
R219  47  [SM-7351-RES-0402]  93.47 23.88 90 top
R220  47  [SM-7351-RES-0402]  94.61 23.88 90 top
R221  47  [SM-7351-RES-0402]  95.76 23.88 90 top
R222  1K  [SM-7351-RES-0402]  59.69 22.35 270 top
R223  33  [SM-7351-RES-0402]  60.83 22.35 270 top
R224  10K  [SM-7351-RES-0402]  65.02 17.4 90 top
R225  10  [SM-7351-RES-0402]  90.68 16.89 180 top
R226  10K  [SM-7351-RES-0402]  97.16 14.61 0 top
R227  14K  [SM-7351-RES-0402]  58.29 13.97 180 top
R228  10K  [SM-7351-RES-0402]  68.2 13.34 0 top
R229  24K, 1%  [SM-7351-RES-0402]  58.29 12.83 180 top
R230  14K  [SM-7351-RES-0402]  58.29 11.68 180 top
R231  10K  [SM-7351-RES-0402]  49.66 11.43 180 top
R232  0  [SM-7351-RES-0402]  92.33 11.3 180 top
R233  100K  [SM-7351-RES-0402]  94.49 11.3 0 top
R234  10K  [SM-7351-RES-0402]  68.2 11.05 0 top
R235  60.4K  [SM-7351-RES-0402]  58.29 10.54 0 top
R236  10K  [SM-7351-RES-0402]  49.66 10.16 180 top
R237  10K  [SM-7351-RES-0402]  68.2 9.91 0 top
R238  0  [SM-7351-RES-0402]  72.39 9.78 270 top
R239  0  [SM-7351-RES-0402]  75.31 9.78 270 top
R240  0  [SM-7351-RES-0402]  76.33 9.78 270 top
R241  0  [SM-7351-RES-0402]  77.34 9.78 90 top
R242  0  [SM-7351-RES-0402]  78.36 9.78 270 top
R243  0  [SM-7351-RES-0402]  80.39 9.78 270 top
R244  10K  [SM-7351-RES-0402]  49.66 9.02 180 top
R245  0  [SM-7351-RES-0402]  83.95 8.89 90 top
R246  0  [SM-7351-RES-0402]  85.09 8.89 90 top
R247  0  [SM-7351-RES-0402]  86.23 8.89 90 top
R248  0  [SM-7351-RES-0402]  87.38 8.89 90 top
R249  0  [SM-7351-RES-0402]  92.33 8.89 270 top
R250  0  [SM-7351-RES-0402]  94.36 8.89 270 top
R251  0  [SM-7351-RES-0402]  95.63 8.89 270 top
R252  0  [SM-7351-RES-0402]  99.31 8.89 270 top
R253  0  [SM-7351-RES-0402]  105.28 8.89 90 top
R254  0  [SM-7351-RES-0402]  107.31 8.89 90 top
R255  0  [SM-7351-RES-0402]  109.22 8.89 90 top
R256  0  [SM-7351-RES-0402]  110.24 8.89 270 top
R257  0  [SM-7351-RES-0402]  111.25 8.89 270 top
R258  0  [SM-7351-RES-0402]  112.27 8.89 90 top
R259  0  [SM-7351-RES-0402]  113.28 8.89 90 top
R260  0  [SM-7351-RES-0402]  115.32 8.89 90 top
R261  0  [SM-7351-RES-0402]  117.35 8.89 90 top
R262  0  [SM-7351-RES-0402]  119.25 8.89 90 top
R263  0  [SM-7351-RES-0402]  121.28 8.89 90 top
R264  0  [SM-7351-RES-0402]  123.32 8.89 90 top
R265  0  [SM-7351-RES-0402]  125.35 8.89 90 top
R266  10K  [SM-7351-RES-0402]  43.31 5.33 90 top
R267  10K  [SM-7351-RES-0402]  44.45 5.33 90 top
R268  150  [SM-7351-RES-0402]  14.22 117.22 180 bottom
R269  220  [SM-7351-RES-0402]  36.83 116.97 90 bottom
R270  220  [SM-7351-RES-0402]  35.69 116.97 90 bottom
R271  150  [SM-7351-RES-0402]  13.97 115.32 90 bottom
R272  150  [SM-7351-RES-0402]  10.29 115.32 90 bottom
R273  0  [SM-7351-RES-0603]  66.29 111.63 270 bottom
R274  100K  [SM-7351-RES-0402]  25.65 111.12 270 bottom
R275  0  [SM-7351-RES-0402]  24.51 111.12 270 bottom
R276  100K  [SM-7351-RES-0402]  22.35 111.12 270 bottom
R277  0  [SM-7351-RES-0402]  21.21 111.12 270 bottom
R278  100K  [SM-7351-RES-0402]  18.8 111.12 270 bottom
R279  0  [SM-7351-RES-0402]  17.65 111.12 90 bottom
R280  150  [SM-7351-RES-0402]  105.03 109.66 270 bottom
R281  150  [SM-7351-RES-0402]  103 109.66 270 bottom
R282  150  [SM-7351-RES-0402]  100.97 109.66 270 bottom
R283  150  [SM-7351-RES-0402]  98.81 109.66 270 bottom
R284  150  [SM-7351-RES-0402]  96.65 109.66 270 bottom
R285  150  [SM-7351-RES-0402]  94.49 109.66 270 bottom
R286  150  [SM-7351-RES-0402]  92.33 109.66 270 bottom
R287  150  [SM-7351-RES-0402]  90.17 109.66 270 bottom
R288  1.2K, MELF  [SMD_MELF0102]  87.5 109.28 270 bottom
R289  1.2K, MELF  [SMD_MELF0102]  84.96 109.28 270 bottom
R290  1.2K, MELF  [SMD_MELF0102]  82.42 109.28 270 bottom
R291  1.2K, MELF  [SMD_MELF0102]  79.88 109.28 270 bottom
R292  1.2K, MELF  [SMD_MELF0102]  77.34 109.28 270 bottom
R293  1.2K, MELF  [SMD_MELF0102]  74.8 109.28 270 bottom
R294  1.2K, MELF  [SMD_MELF0102]  72.26 109.28 270 bottom
R295  1.2K, MELF  [SMD_MELF0102]  69.72 109.28 270 bottom
R296  0  [SM-7351-RES-0402]  65.79 109.22 180 bottom
R297  10K  [SM-7351-RES-0402]  133.54 106.61 90 bottom
R298  15K,1%  [SM-7351-RES-0402]  63.12 106.55 0 bottom
R299  0  [SM-7351-RES-0603]  67.56 106.17 180 bottom
R300  10K  [SM-7351-RES-0402]  85.34 105.92 180 bottom
R301  30.1K  [SM-7351-RES-0402]  113.16 105.72 180 bottom
R302  49.9  [SM-7351-RES-0402]  63.12 105.03 180 bottom
R303  0  [SM-7351-RES-0603]  116.84 104.71 270 bottom
R304  0  [SM-7351-RES-0402]  122.36 104.33 90 bottom
R305  10K  [SM-7351-RES-0402]  120.78 104.27 270 bottom
R306  39K  [SM-7351-RES-0402]  112.65 104.07 270 bottom
R307  1M  [SM-7351-RES-0402]  21.21 104.01 0 bottom
R308  0  [SM-7351-RES-0402]  19.05 102.74 90 bottom
R309  0  [SM-7351-RES-0402]  109.22 102.23 180 bottom
R310  0  [SM-7351-RES-0402]  3.81 102.11 180 bottom
R311  33  [SM-7351-RES-0402]  18.54 101.09 180 bottom
R312  33  [SM-7351-RES-0402]  18.54 99.95 180 bottom
R313  0  [SM-7351-RES-0603]  128.84 99.63 0 bottom
R314  10K  [SM-7351-RES-0402]  67.69 99.63 270 bottom
R315  10K  [SM-7351-RES-0402]  66.29 99.63 270 bottom
R316  10K  [SM-7351-RES-0402]  64.9 99.63 270 bottom
R317  10K  [SM-7351-RES-0402]  63.5 99.63 270 bottom
R318  10K  [SM-7351-RES-0402]  62.1 99.63 270 bottom
R319  10K  [SM-7351-RES-0402]  60.71 99.63 270 bottom
R320  10K  [SM-7351-RES-0402]  59.31 99.63 270 bottom
R321  10K  [SM-7351-RES-0402]  57.91 99.63 270 bottom
R322  25K  [SM-7351-RES-0603]  77.6 98.87 0 bottom
R323  33  [SM-7351-RES-0402]  18.54 98.42 180 bottom
R324  0  [SM-7351-RES-0402]  103.47 97.63 90 bottom
R325  0  [SM-7351-RES-0402]  102.33 97.63 90 bottom
R326  0  [SM-7351-RES-0603]  114.68 97.41 270 bottom
R327  0  [SM-7351-RES-0603]  112.9 97.41 270 bottom
R328  10K  [SM-7351-RES-0402]  66.93 95.82 270 bottom
R329  10K  [SM-7351-RES-0402]  65.53 95.82 270 bottom
R330  10K  [SM-7351-RES-0402]  63.88 95.82 270 bottom
R331  10K  [SM-7351-RES-0402]  62.48 95.82 270 bottom
R332  10K  [SM-7351-RES-0402]  61.09 95.82 270 bottom
R333  10K  [SM-7351-RES-0402]  59.69 95.82 270 bottom
R334  10K  [SM-7351-RES-0402]  58.29 95.82 270 bottom
R335  10K  [SM-7351-RES-0402]  56.9 95.82 270 bottom
R336  10K  [SM-7351-RES-0402]  49.78 95.63 180 bottom
R337  0  [SM-7351-RES-0402]  33.4 95.63 0 bottom
R338  49.9  [SMD_MELF0102]  78.77 95.58 180 bottom
R339  0  [SM-7351-RES-0402]  33.4 94.49 0 bottom
R340  10K  [SM-7351-RES-0402]  68.71 94.29 270 bottom
R341  10K  [SM-7351-RES-0402]  71.88 94.23 270 bottom
R342  10K  [SM-7351-RES-0402]  70.74 94.23 270 bottom
R343  10K  [SM-7351-RES-0402]  115.95 93.98 90 bottom
R344  0  [SM-7351-RES-0402]  33.4 93.34 0 bottom
R345  10K  [SM-7351-RES-0402]  49.78 92.84 180 bottom
R346  0  [SM-7351-RES-0603]  25.4 92.55 270 bottom
R347  10K  [SM-7351-RES-0402]  129.16 92.46 180 bottom
R348  0  [SM-7351-RES-0402]  2.54 92.46 270 bottom
R349  0  [SM-7351-RES-0402]  33.4 92.2 0 bottom
R350  0  [SM-7351-RES-0402]  129.16 91.31 180 bottom
R351  0  [SM-7351-RES-0402]  33.4 90.93 0 bottom
R352  0  [SM-7351-RES-0402]  2.54 90.3 90 bottom
R353  4.7K  [SM-7351-RES-0402]  37.08 89.66 180 bottom
R354  0  [SM-7351-RES-0402]  104.14 88.52 270 bottom
R355  0  [SM-7351-RES-0402]  103 88.52 270 bottom
R356  0  [SM-7351-RES-0402]  101.73 88.52 270 bottom
R357  0  [SM-7351-RES-0402]  37.08 88.52 180 bottom
R358  0  [SM-7351-RES-0603]  95.5 88.01 90 bottom
R359  0  [SM-7351-RES-0402]  116.59 87.12 90 bottom
R360  0  [SM-7351-RES-0402]  118.11 86.61 0 bottom
R361  100K  [SM-7351-RES-0402]  31.12 86.23 270 bottom
R362  4.87K  [SM-7351-RES-0402]  24.26 86.23 90 bottom
R363  0  [SM-7351-RES-0402]  105.54 85.85 90 bottom
R364  0  [SM-7351-RES-0402]  104.14 85.85 90 bottom
R365  22  [SM-7351-RES-0402]  47.62 85.6 270 bottom
R366  1K  [SM-7351-RES-0402]  46.48 85.6 90 bottom
R367  22  [SM-7351-RES-0402]  45.34 85.6 270 bottom
R368  22  [SM-7351-RES-0402]  44.2 85.6 270 bottom
R369  1K  [SM-7351-RES-0402]  43.05 85.6 90 bottom
R370  22  [SM-7351-RES-0402]  41.91 85.6 270 bottom
R371  22  [SM-7351-RES-0402]  40.77 85.6 270 bottom
R372  1K  [SM-7351-RES-0402]  39.62 85.6 90 bottom
R373  22  [SM-7351-RES-0402]  38.48 85.6 270 bottom
R374  0  [SM-7351-RES-0402]  37.34 85.6 270 bottom
R375  0  [SM-7351-RES-0402]  90.55 85.09 90 bottom
R376  0  [SM-7351-RES-0402]  127 84.58 0 bottom
R377  0  [SM-7351-RES-0402]  60.45 84.58 0 bottom
R378  0  [SM-7351-RES-0402]  57.02 84.58 0 bottom
R379  0  [SM-7351-RES-0603]  112.84 84.2 0 bottom
R380  0  [SM-7351-RES-0402]  19.43 83.82 270 bottom
R381  0  [SM-7351-RES-0402]  127 83.57 0 bottom
R382  0  [SM-7351-RES-0402]  85.34 83.57 270 bottom
R383  0  [SM-7351-RES-0402]  84.33 83.57 90 bottom
R384  0  [SM-7351-RES-0402]  83.19 83.57 270 bottom
R385  0  [SM-7351-RES-0402]  82.17 83.57 90 bottom
R386  33  [SM-7351-RES-0402]  78.74 83.57 90 bottom
R387  33  [SM-7351-RES-0402]  77.09 83.57 90 bottom
R388  0  [SM-7351-RES-0402]  73.28 83.44 90 bottom
R389  100  [SM-7351-RES-0402]  136.14 83.31 180 bottom
R390  0  [SM-7351-RES-0402]  60.45 83.31 0 bottom
R391  0  [SM-7351-RES-0402]  57.02 83.31 0 bottom
R392  10K  [SM-7351-RES-0402]  46.48 82.93 90 bottom
R393  10K  [SM-7351-RES-0402]  45.34 82.93 90 bottom
R394  1K  [SM-7351-RES-0402]  44.2 82.93 90 bottom
R395  10K  [SM-7351-RES-0402]  43.05 82.93 90 bottom
R396  10K  [SM-7351-RES-0402]  41.91 82.93 90 bottom
R397  1K  [SM-7351-RES-0402]  40.77 82.93 90 bottom
R398  1K  [SM-7351-RES-0402]  39.62 82.93 90 bottom
R399  10K  [SM-7351-RES-0402]  38.48 82.93 90 bottom
R400  10K  [SM-7351-RES-0402]  37.34 82.93 90 bottom
R401  0  [SM-7351-RES-0603]  33.53 82.3 270 bottom
R402  4.7K  [SM-7351-RES-0402]  136.08 82.04 0 bottom
R403  4.7K  [SM-7351-RES-0402]  130.94 82.04 0 bottom
